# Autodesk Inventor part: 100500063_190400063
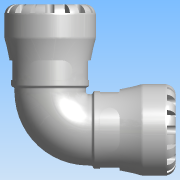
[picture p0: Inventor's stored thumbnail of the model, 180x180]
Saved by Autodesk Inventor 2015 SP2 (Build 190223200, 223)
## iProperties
Created: 2016-12
Part Number: 100500063_190400063
Material: PVC-Piping
Description: PLASSON 90° ELBOW 63X63 SERIES 1
Document SubType Name: Modeling
Designer: KIM
Mass: 664.223 g
Surface Area: 733.008 cm^2
Volume: 474.445 cm^3
Density: 1.4 g/cm^3
Appearance: Smooth - White
Author: KIM
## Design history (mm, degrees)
derived "1005.ipt"
feature "Solid1::1005.ipt"
tag "TaggingFeature1"
body "Solid1"
other parameters: "d1" = 37.8, "d2" = 63, "d3" = 78.75, "d4" = 103, "d8" = 87.55, "d13" = 9.7, "d14" = 9.7, "d15" = 0, "d17" = 360 deg, "d19" = 8 deg, "d20" = 1.26, "d21" = 1.26, "d22" = 8 deg, "d24" = 0, "d26" = 360 deg, "d33" = 10.3, "d43" = 80.34, "d51" = 1.03, "d54" = 22.05, "d55" = 13.86, "d57" = 19.012, "d58" = 0, "d74" = 0, "d77" = 5.25, "d82" = 1.26, "d115" = 360 deg, "d207" = 90 deg, "d228" = 18.7425, "d247" = 2.06, "d248" = 5.4, "d268" = 48.1525, "d269" = 5.4, "d270" = 141, "d272" = 90 deg, "d274" = 0, "d275" = 0, "d_" = 63, "E_" = 103, "A_" = 141, "d9" = 12.125, "d11" = 103, "d12" = 78.75
